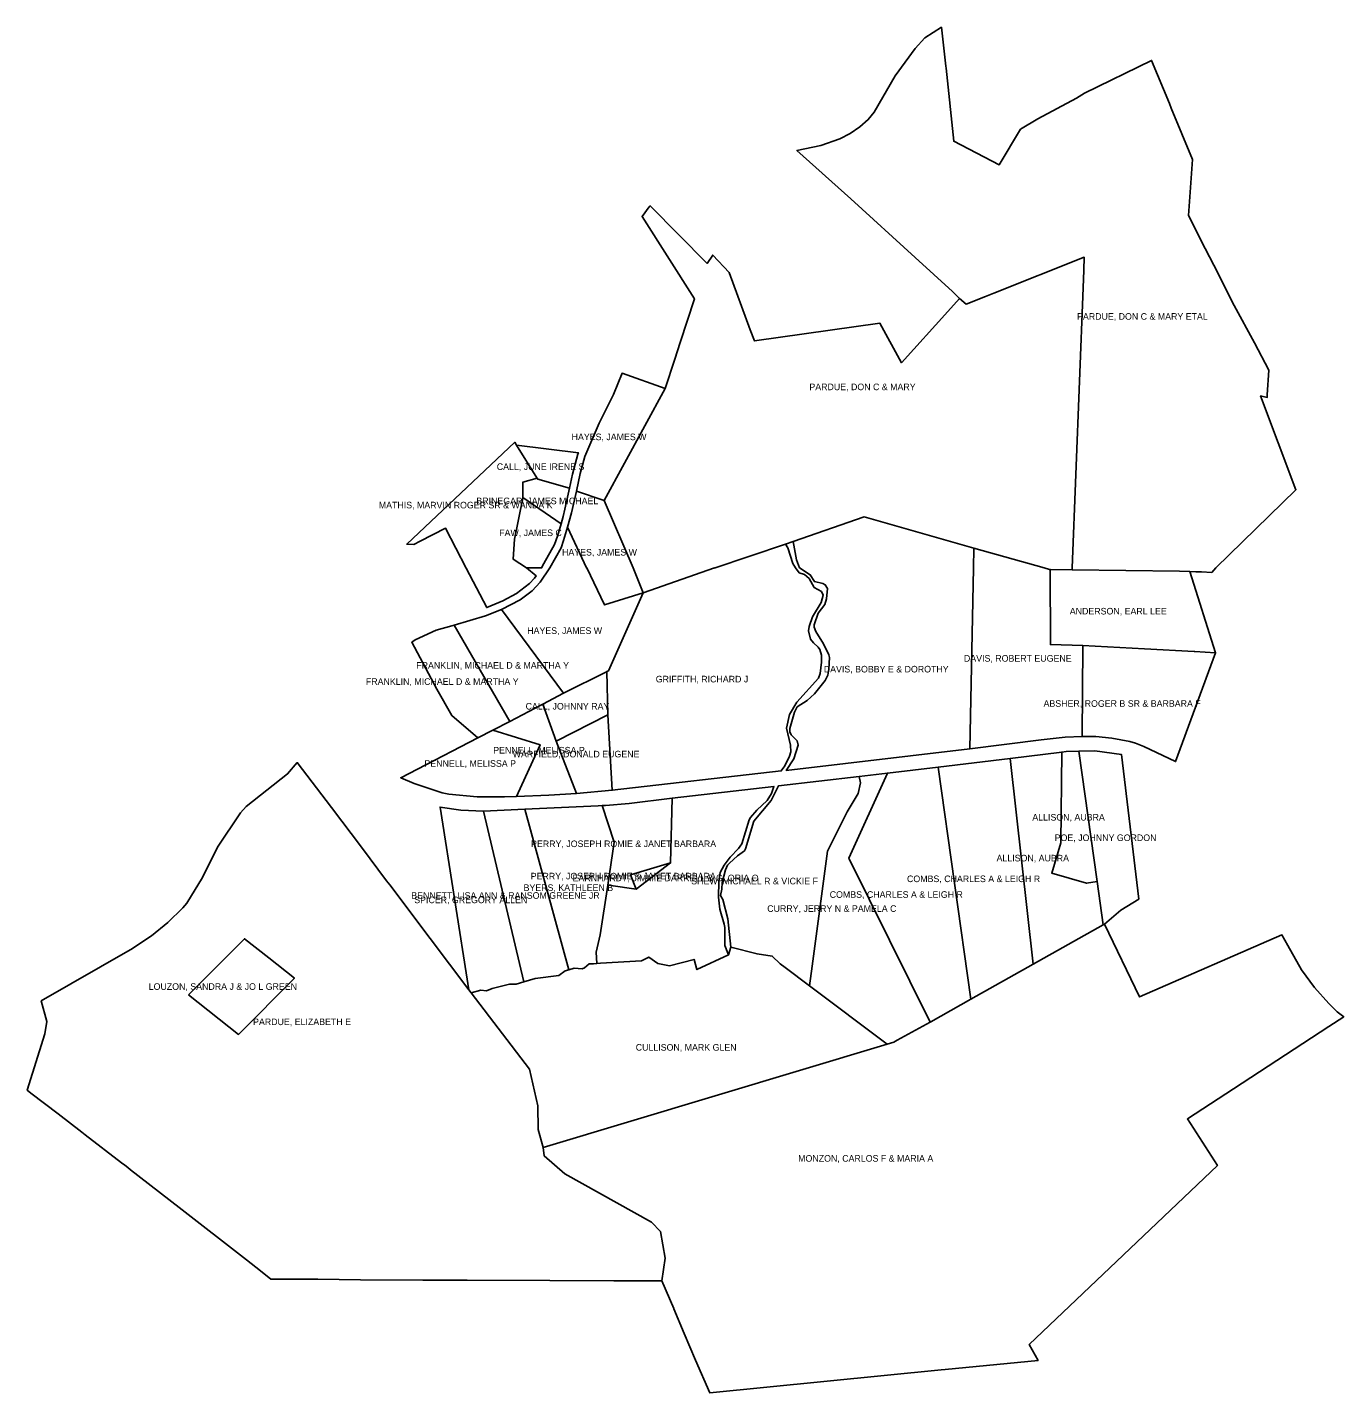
# Model space of a CAD drawing. Extents: x 1379570 to 1385062, y 881561 to 887254.
import ezdxf

# ---------------------------------------------------------------- set-up
doc = ezdxf.new("R2010")
doc.units = 0
doc.layers.add('WILKES_2010PARCELS', color=7, linetype='Continuous')

msp = doc.modelspace()

# ---------------------------------------------------------------- linework, layer by layer
at = {"layer": 'WILKES_2010PARCELS'}
for points in [[(1383928.6, 885000.1), (1383974.4, 886167.6), (1383977.1, 886241.4), (1383979.1, 886295.6), (1383602.2, 886145.9), (1383567.5, 886132.1), (1383486.5, 886099.9), (1383458.9, 886124.2), (1383437.6, 886144.9), (1383429.6, 886152.7), (1383274, 886294.8), (1383005.9, 886539.3), (1382780.6, 886741.2), (1382879.9, 886761.1), (1382959.4, 886789), (1383002, 886812.1), (1383042.8, 886839.2), (1383078.2, 886869.4), (1383103.4, 886900.2), (1383190.4, 887052.5), (1383273.6, 887165.4), (1383314.1, 887210.6), (1383383.6, 887254.4), (1383401.6, 887092), (1383402.5, 887083.7), (1383434.9, 886779.4), (1383624.6, 886681.4), (1383713.9, 886829.4), (1383786.2, 886873.4), (1383946.4, 886959.1), (1383980, 886979.5), (1384259.8, 887116), (1384334.6, 886936.1), (1384342.4, 886917.6), (1384431.4, 886703.8), (1384414.1, 886469.2), (1384483.9, 886332.1), (1384519.4, 886262.2), (1384604.2, 886095.1), (1384688.8, 885938.2), (1384748.7, 885825.3), (1384742.8, 885721.7), (1384742.5, 885711.4), (1384714.7, 885717.5), (1384861.9, 885326.4), (1384528.5, 885000)], [(1382098.1, 884999.9), (1381976.5, 885281.5), (1382231.5, 885748.1), (1382271.1, 885870.3), (1382293.8, 885940.1), (1382352.8, 886122.3), (1382134.5, 886465), (1382164.6, 886505.4), (1382168.2, 886510.3), (1382405.6, 886269.9), (1382429.6, 886304.3), (1382497.6, 886231.6), (1382585.9, 885992.6), (1382602.9, 885946.6), (1383126.5, 886020.4), (1383217.1, 885855.8), (1383409.8, 886069.6), (1383458.9, 886124.2), (1383486.5, 886099.9), (1383567.5, 886132.1), (1383602.2, 886145.9), (1383979.1, 886295.6), (1383977.1, 886241.4), (1383974.4, 886167.6), (1383928.6, 885000.1)], [(1381401, 884999.8), (1381314.4, 885166.2), (1381208.5, 885111.6), (1381182.5, 885098.1), (1381153.2, 885099.3), (1381603.5, 885524.4), (1381611.2, 885511.9), (1381696.1, 885375.2), (1381696.5, 885374.7), (1381637, 885357.2), (1381637, 885290.9), (1381601.8, 885120.6), (1381597.4, 885036.1), (1381652.9, 885000)], [(1381903, 884999.9), (1381823.4, 885169.7), (1381840.8, 885230), (1381860.4, 885320.7), (1381976.5, 885281.5), (1382098.1, 884999.9)], [(1383812.5, 885000), (1383518.5, 885083.2), (1383061.1, 885213.8), (1382764.6, 885110.3), (1382733.1, 885099.3), (1382435.2, 884999.8)], [(1382791.6, 885000.1), (1382778.5, 885033.5), (1382764.6, 885110.3), (1383061.1, 885213.8), (1383518.5, 885083.2), (1383516.6, 884999.4)], [(1381750, 885000.2), (1381796.4, 885084.4), (1381807.4, 885114.5), (1381823.4, 885169.7), (1381903, 884999.9)], [(1382435.2, 884999.8), (1382733.1, 885099.3), (1382742.5, 885083.4), (1382763, 885018.4), (1382774.6, 885000.2)], [(1383516.6, 884999.4), (1383518.5, 885083.2), (1383812.5, 885000)], [(1381652.4, 885000), (1381692.4, 884967.4), (1381685.6, 884957.9), (1381665.6, 884935.6), (1381610.1, 884893.1), (1381554.1, 884862.6), (1381486.9, 884834.5), (1381401, 884999.8)], [(1381903.5, 884999.9), (1381977.5, 884846.1), (1382138.8, 884896.7), (1381994, 884571.5), (1381985.6, 884567.3), (1381807.4, 884477.4), (1381547.6, 884827.3), (1381626.4, 884867.7), (1381675.5, 884904.2), (1381709.9, 884940.2), (1381750, 885000.2)], [(1382098, 884999.9), (1382138.8, 884896.7), (1381977.5, 884846.1), (1381903.5, 884999.9)], [(1382774.6, 885000.2), (1382790.5, 884980.1), (1382811.5, 884973), (1382831.2, 884955.8), (1382852.5, 884918.9), (1382883.1, 884901.2), (1382890.2, 884887.1), (1382881.2, 884856), (1382846, 884795.6), (1382831.9, 884755.9), (1382829.5, 884738.4), (1382836.6, 884703.6), (1382849.6, 884687.4), (1382869.8, 884669.9), (1382875.8, 884660.1), (1382882.4, 884635.8), (1382883.6, 884607.4), (1382877.5, 884560.5), (1382870.4, 884540.9), (1382780.5, 884440.2), (1382749.5, 884388.8), (1382737.4, 884332.5), (1382754, 884261.1), (1382755.4, 884233.4), (1382749.5, 884215), (1382730.1, 884175.6), (1382715.4, 884153.6), (1382010.4, 884072.9), (1381991.6, 884387.7), (1381988, 884568.5), (1381994, 884571.5), (1382138.8, 884896.7), (1382436.1, 884999.9)], [(1382436.1, 884999.9), (1382138.8, 884896.7), (1382098, 884999.9)], [(1383516.6, 884999.4), (1383501.4, 884246.4), (1382736.2, 884156.2), (1382767.8, 884203.6), (1382786, 884261.6), (1382780.9, 884278.8), (1382756, 884304.9), (1382750.9, 884316.1), (1382750.9, 884330.6), (1382770.5, 884399.3), (1382781.5, 884420.8), (1382823, 884447), (1382853.6, 884475.2), (1382898.1, 884531), (1382909, 884552.9), (1382914, 884578.6), (1382916.2, 884626.2), (1382913.2, 884638.3), (1382891.6, 884683.5), (1382859.9, 884734.9), (1382852.8, 884752.8), (1382852, 884763.5), (1382868.8, 884811.9), (1382896.8, 884848), (1382903.4, 884871.7), (1382908.6, 884914), (1382899, 884929.8), (1382888.8, 884935.8), (1382853.6, 884942.9), (1382836, 884971.4), (1382791.6, 885000.1)], [(1383812.5, 885000), (1383834.6, 884993.8), (1383837.6, 884993.8), (1383838, 884680.7), (1383972.7, 884677.1), (1383970.1, 884297.9), (1383899.6, 884294.2), (1383799.2, 884283.9), (1383501.4, 884246.4), (1383516.6, 884999.4)], [(1383928.6, 885000.1), (1383928.1, 884992.6), (1383837.6, 884993.8), (1383834.6, 884993.8), (1383812.5, 885000)], [(1384528.5, 885000), (1384510.8, 884981.4), (1384467.9, 884983.4), (1384445.2, 884984.2), (1384419.4, 884985.1), (1384377.2, 884986.4), (1383928.1, 884992.6), (1383928.6, 885000.1)], [(1379999.8, 883407.5), (1380001.6, 883408.7), (1380087.8, 883466.4), (1380156.5, 883521.7), (1380219.5, 883583), (1380234.9, 883602.4), (1380300.6, 883708.9), (1380363.5, 883835.2), (1380459.5, 883979.1), (1380483.6, 884005.9), (1380655.9, 884141.6), (1380695.8, 884188.3), (1380838.6, 884001.9), (1380964.2, 883835.2), (1381069.1, 883696.1), (1381082.5, 883678.4), (1381251.1, 883454.7), (1381411.8, 883241.6), (1381421.2, 883228.9), (1381665.1, 882909.6), (1381699.9, 882756.7), (1381701.1, 882659.2), (1381722.6, 882583.8), (1381726.2, 882548.6), (1381812.8, 882473.1), (1382174.4, 882272.9), (1382211.2, 882233.7), (1382231.5, 882121.6), (1382216.8, 882027), (1382016.9, 882027.4), (1381749.4, 882029), (1381404.5, 882029.9), (1381220.1, 882030.4), (1380959.6, 882032), (1380781.6, 882033.9), (1380688.6, 882034.6), (1380586.6, 882035), (1380543.5, 882068.7), (1380484.2, 882114.9), (1380203, 882333.6), (1380000.5, 882490.8)], [(1385000, 883088.1), (1384602.4, 882827.8), (1384409.6, 882702.6), (1384535, 882508.6), (1383749.8, 881762.2), (1383786.9, 881695.9), (1383399.1, 881657.8), (1383381.9, 881656.1), (1382417.2, 881561.2), (1382357.2, 881696.9), (1382310.1, 881808.1), (1382267.5, 881910.8), (1382266.6, 881912.7), (1382216.8, 882027), (1382231.5, 882121.6), (1382211.2, 882233.7), (1382174.4, 882272.9), (1381812.8, 882473.1), (1381726.2, 882548.6), (1381722.6, 882583.8), (1383157.5, 883014.9), (1383185, 883023.2), (1383198.4, 883030.9), (1383336.5, 883106.5), (1383338.6, 883107.6), (1383505.6, 883201.5), (1383766.6, 883348.2), (1384058.6, 883512.5), (1384063.4, 883515.2), (1384209.1, 883211.4), (1384803.9, 883470.1), (1384828.4, 883426.2), (1384885.6, 883324), (1384939.8, 883250.1), (1384999.9, 883184.6)], [(1379989.2, 882499.9), (1379977, 882509.4), (1379962.9, 882520.3), (1379811.6, 882636.9), (1379798, 882647.5), (1379698.2, 882724.4), (1379585.4, 882809.7), (1379570, 882822), (1379642.6, 883058), (1379650.9, 883108.3), (1379628.5, 883194.9), (1379999.8, 883407.5)], [(1384999.9, 883184.6), (1385034, 883149.8), (1385061.5, 883128.4), (1385000, 883088.1)], [(1379962.9, 882520.3), (1379977, 882509.4), (1379989.2, 882499.9)], [(1380000.5, 882490.8), (1379989.2, 882499.9)]]:
    msp.add_lwpolyline(points, dxfattribs=at)
for points in [[(1381876.2, 885394.1), (1381895.5, 885464.8), (1381956, 885604.4), (1382015.1, 885723.1), (1382051.4, 885811.8), (1382231.5, 885748.1), (1381976.5, 885281.5), (1381860.4, 885320.7)], [(1381696.5, 885374.7), (1381696.1, 885375.2), (1381611.2, 885511.9), (1381869.2, 885480.1), (1381867, 885474.8), (1381844.1, 885390.6), (1381831.8, 885332.8), (1381699.1, 885370.8)], [(1381637, 885293.4), (1381637, 885357.2), (1381696.5, 885374.7), (1381699.1, 885370.8), (1381831.8, 885332.8), (1381813, 885244.7), (1381804.9, 885215.1), (1381796.4, 885184.4)], [(1381652.9, 885000), (1381597.4, 885036.1), (1381601.8, 885120.6), (1381637, 885290.9), (1381637, 885293.4), (1381796.4, 885184.4), (1381782.2, 885132.9), (1381769.1, 885097.2), (1381724.9, 885018.6), (1381715.2, 885000.1)], [(1383838, 884680.7), (1383837.6, 884993.8), (1383928.1, 884992.6), (1384377.2, 884986.4), (1384419.4, 884985.1), (1384526.9, 884645.9), (1384440, 884651.7), (1384437, 884651.8), (1384230.5, 884662.7), (1383972.7, 884677.1)], [(1381582.8, 884360.2), (1381350.5, 884761.1), (1381482.1, 884800), (1381547.6, 884827.3), (1381807.4, 884477.4), (1381720.2, 884432.6), (1381715.2, 884430)], [(1381278.1, 884495.3), (1381173.9, 884690.5), (1381188.2, 884700.1), (1381275.6, 884740.1), (1381341.1, 884758.6), (1381350.5, 884761.1), (1381582.8, 884360.2), (1381512.4, 884323.8), (1381449.6, 884291.4), (1381340.5, 884384.4)], [(1383970.1, 884297.9), (1383972.7, 884677.1), (1384230.5, 884662.7), (1384437, 884651.8), (1384440, 884651.7), (1384526.9, 884645.9), (1384360, 884192.5), (1384228.4, 884255.4), (1384193.4, 884269.8), (1384168.9, 884276.1), (1384094.6, 884290.2), (1384027.5, 884297.7)], [(1381776.2, 884278.4), (1381720.2, 884432.6), (1381807.4, 884477.4), (1381985.6, 884567.3), (1381988, 884568.5), (1381991.6, 884387.7)], [(1381610.5, 884047.8), (1381709.2, 884263.2), (1381512.4, 884323.8), (1381582.8, 884360.2), (1381715.2, 884430), (1381720.2, 884432.6), (1381776.2, 884278.4), (1381860.9, 884060.2), (1381745, 884052.7)], [(1381860.9, 884060.2), (1381776.2, 884278.4), (1381991.6, 884387.7), (1382010.4, 884072.9)], [(1381198.2, 884161.7), (1381449.6, 884291.4), (1381512.4, 884323.8), (1381709.2, 884263.2), (1381610.5, 884047.8), (1381561.2, 884046.1), (1381446.2, 884045.6), (1381327.8, 884056.9), (1381300.4, 884062.9), (1381183.6, 884100.7), (1381128.1, 884125.4)], [(1383766.6, 883348.2), (1383670.4, 884206.2), (1383885, 884232.1), (1383881.2, 883854.4), (1383843.6, 883727.9), (1383989, 883685.2), (1384033.2, 883693.1), (1384058.6, 883512.5)], [(1383881.2, 883854.4), (1383885, 884232.1), (1383904.4, 884234.4), (1383956.9, 884235.9), (1384033.2, 883693.1), (1383989, 883685.2), (1383843.6, 883727.9)], [(1384033.2, 883693.1), (1383956.9, 884235.9), (1384024, 884237.7), (1384134.1, 884222.9), (1384206.8, 883619.1), (1384131.7, 883573.8), (1384063.4, 883515.2), (1384058.6, 883512.5)], [(1383336.5, 883106.5), (1382997, 883790.5), (1383158, 884144.6), (1383370.2, 884170.1), (1383505.6, 883201.5), (1383338.6, 883107.6)], [(1383505.6, 883201.5), (1383370.2, 884170.1), (1383670.4, 884206.2), (1383766.6, 883348.2)], [(1382505.1, 883418.2), (1382492.9, 883536.6), (1382471.9, 883617.1), (1382461.9, 883634.8), (1382467.5, 883661), (1382468.5, 883687.9), (1382482.4, 883740.8), (1382491.6, 883761.1), (1382499, 883769.6), (1382533.1, 883799.9), (1382561.8, 883820.2), (1382566.6, 883828.6), (1382601.5, 883944.6), (1382672.5, 884029.8), (1382703.2, 884091.4), (1383040.4, 884130.8), (1383045.4, 884104.7), (1383035.4, 884060.1), (1382990.4, 883982.9), (1382908.2, 883819), (1382846.5, 883360.8), (1382843.6, 883339.3), (1382832.6, 883258.2), (1382731, 883334.4), (1382710, 883349.9), (1382677.9, 883381.7), (1382614.5, 883390.6)], [(1382846.5, 883360.8), (1382908.2, 883819), (1382990.4, 883982.9), (1383035.4, 884060.1), (1383045.4, 884104.7), (1383040.4, 884130.8), (1383158, 884144.6), (1382997, 883790.5), (1383336.5, 883106.5), (1383198.4, 883030.9), (1383185, 883023.2), (1383157.5, 883014.9), (1382832.6, 883258.2), (1382843.6, 883339.3)], [(1382110.1, 883660.2), (1382253.2, 883770.1), (1382260.5, 884039.6), (1382684.8, 884089.1), (1382674.2, 884059.9), (1382656.4, 884030.4), (1382612.8, 883990.5), (1382586.6, 883959.4), (1382581.2, 883949.7), (1382550.5, 883849.3), (1382537.4, 883829.9), (1382502.6, 883793.8), (1382477.6, 883761.3), (1382460.2, 883730.9), (1382454.7, 883692.9), (1382453.1, 883628), (1382459.2, 883577.3), (1382477.6, 883515.1), (1382480, 883500.5), (1382479.8, 883426), (1382492.4, 883393.9), (1382495, 883386.8), (1382363.1, 883325.7), (1382351.5, 883367.8), (1382249.6, 883341.4), (1382200.6, 883350.6), (1382162.9, 883377.2), (1382131.9, 883361.2), (1381961.4, 883351.7), (1381946.1, 883350.9), (1381943, 883397.7), (1381959.2, 883469.8), (1381991.1, 883677.7), (1382004.8, 883675.8)], [(1382018.6, 883856.6), (1381968.2, 884009), (1381981.6, 884010.1), (1382080.2, 884018.6), (1382260.5, 884039.6), (1382253.2, 883770.1), (1382086.2, 883721.1), (1382110.1, 883660.2), (1382004.8, 883675.8), (1381991.1, 883677.7)], [(1381411.8, 883241.6), (1381291.9, 884003.2), (1381378.2, 883990.1), (1381473.5, 883985.7), (1381641.1, 883274.8), (1381609.5, 883265.1), (1381581.2, 883264.1), (1381509.8, 883246.1), (1381485.7, 883236.9), (1381461.8, 883239.7), (1381421.2, 883228.9)], [(1381641.1, 883274.8), (1381473.5, 883985.7), (1381646, 883993.8), (1381829.1, 883324.6), (1381813.9, 883320.7), (1381786.9, 883300.5), (1381688.5, 883287.9)], [(1381829.1, 883324.6), (1381646, 883993.8), (1381950.8, 884008.2), (1381968.2, 884009), (1382018.6, 883856.6), (1381991.1, 883677.7), (1381959.2, 883469.8), (1381943, 883397.7), (1381946.1, 883350.9), (1381931.4, 883350), (1381914.2, 883348.9), (1381894.6, 883332.2), (1381884.5, 883329.2), (1381852, 883331.2)], [(1382110.1, 883660.2), (1382086.2, 883721.1), (1382253.2, 883770.1)], [(1380243.1, 883220.1), (1380301.5, 883278.9), (1380475.6, 883454.2), (1380577, 883373.9), (1380684, 883289.2), (1380451.5, 883055.1)], [(1381665.1, 882909.6), (1381421.2, 883228.9), (1381461.8, 883239.7), (1381485.7, 883236.9), (1381509.8, 883246.1), (1381581.2, 883264.1), (1381609.5, 883265.1), (1381641.1, 883274.8), (1381688.5, 883287.9), (1381786.9, 883300.5), (1381813.9, 883320.7), (1381829.1, 883324.6), (1381852, 883331.2), (1381884.5, 883329.2), (1381894.6, 883332.2), (1381914.2, 883348.9), (1381931.4, 883350), (1381946.1, 883350.9), (1381961.4, 883351.7), (1382131.9, 883361.2), (1382162.9, 883377.2), (1382200.6, 883350.6), (1382249.6, 883341.4), (1382351.5, 883367.8), (1382363.1, 883325.7), (1382495, 883386.8), (1382505.1, 883418.2), (1382614.5, 883390.6), (1382677.9, 883381.7), (1382710, 883349.9), (1382731, 883334.4), (1382832.6, 883258.2), (1383157.5, 883014.9), (1381722.6, 882583.8), (1381701.1, 882659.2), (1381699.9, 882756.7)]]:
    msp.add_lwpolyline(points, close=True, dxfattribs=at)

# ---------------------------------------------------------------- texts
for s, p in [('PARDUE, DON C & MARY ETAL', (1383949.1, 886035)), ('PARDUE, DON C & MARY', (1382832.6, 885741.3)), ('HAYES, JAMES W', (1381840.7, 885532.9)), ('CALL, JUNE IRENE S', (1381528.5, 885408.6)), ('BRINEGAR, JAMES MICHAEL', (1381443.4, 885265.8)), ('MATHIS, MARVIN ROGER SR & WANDA K', (1381036.4, 885248.4)), ('FAW, JAMES C', (1381538.6, 885132.9)), ('HAYES, JAMES W', (1381800.8, 885051.8)), ('ANDERSON, EARL LEE', (1383918.9, 884806.1)), ('HAYES, JAMES W', (1381655.4, 884725)), ('FRANKLIN, MICHAEL D & MARTHA Y', (1381192.6, 884580)), ('DAVIS, ROBERT EUGENE', (1383477.3, 884609.4)), ('GRIFFITH, RICHARD J', (1382191.7, 884522.8)), ('DAVIS, BOBBY E & DOROTHY', (1382892.7, 884564.4)), ('FRANKLIN, MICHAEL D & MARTHA Y', (1380982.5, 884512.5)), ('CALL, JOHNNY RAY', (1381648.8, 884409.7)), ('ABSHER, ROGER B SR & BARBARA F', (1383809.4, 884421)), ('PENNELL, MELISSA P', (1381513.6, 884226.4)), ('WARFIELD, DONALD EUGENE', (1381594.8, 884210.2)), ('PENNELL, MELISSA P', (1381226.7, 884170.9)), ('ALLISON, AUBRA', (1383762.6, 883946.8)), ('POE, JOHNNY GORDON', (1383855.9, 883861.4)), ('PERRY, JOSEPH ROMIE & JANET BARBARA', (1381671.6, 883836.2)), ('ALLISON, AUBRA', (1383613.3, 883776.4)), ('PERRY, JOSEPH ROMIE & JANET BARBARA', (1381670.2, 883701.4)), ('EARNHARDT, JIMMIE DARRELL & GLORIA O', (1381844.8, 883693.7)), ('SHEW, MICHAEL R & VICKIE F', (1382339.6, 883680.8)), ('COMBS, CHARLES A & LEIGH R', (1383239.8, 883690.1)), ('BENNETT, LISA ANN & RANSOM GREENE JR', (1381171.7, 883620.6)), ('BYERS, KATHLEEN B', (1381640.3, 883653.1)), ('COMBS, CHARLES A & LEIGH R', (1382917.3, 883624.6)), ('SPICER, GREGORY ALLEN', (1381184.2, 883602.3)), ('CURRY, JERRY N & PAMELA C', (1382656.7, 883566)), ('LOUZON, SANDRA J & JO L GREEN', (1380076.5, 883240.9)), ('PARDUE, ELIZABETH E', (1380511.9, 883093.9)), ('CULLISON, MARK GLEN', (1382108.2, 882987.3)), ('MONZON, CARLOS F & MARIA A', (1382785.8, 882524.4))]:
    msp.add_text(s, height=27.481, dxfattribs=at).set_placement(p)

doc.saveas('drawing.dxf')
